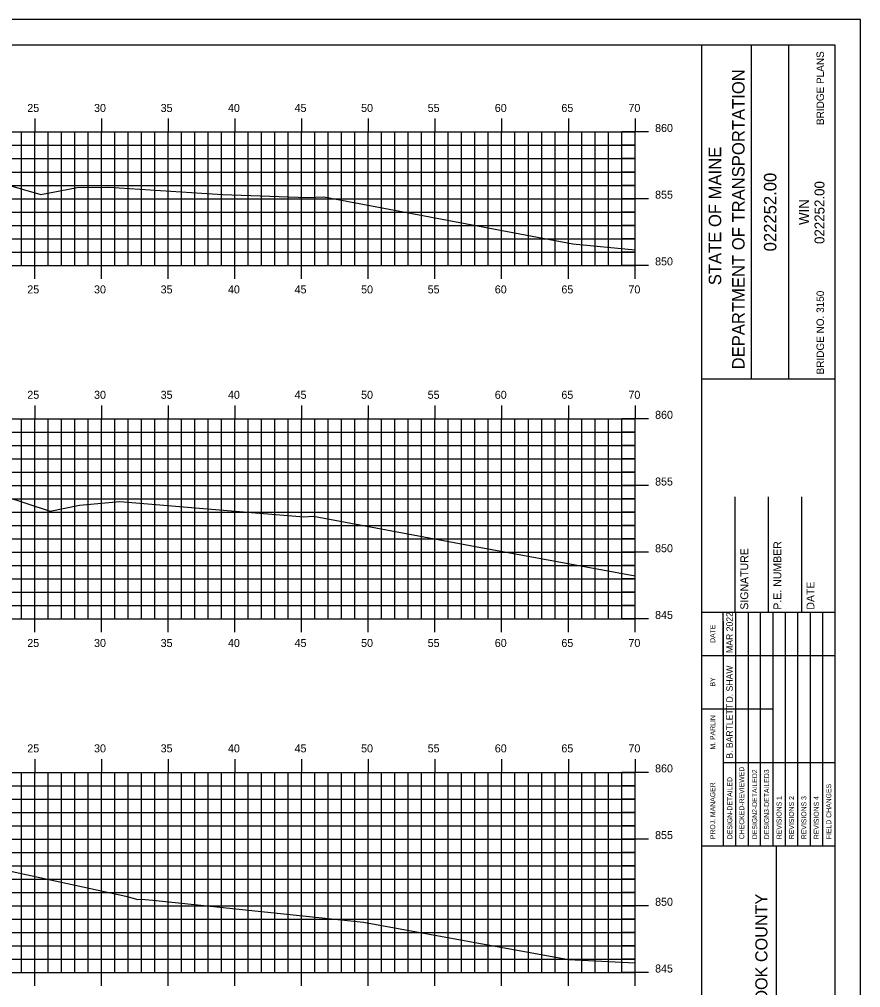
# Model space of a CAD drawing. Extents: x 2194738 to 2195190, y 863888 to 863998.
# Drawn here: x 2194944.1 to 2195007.2, y 863925.8 to 863998.4 of the extents above; entities that cross this region are included whole.
import ezdxf

# ---------------------------------------------------------------- set-up
doc = ezdxf.new("R2010")
doc.units = 0
for name, color, linetype in [('BORDER', 7, 'Continuous'), ('BRIDGE_TITLE', 7, 'Continuous'), ('H_V ANNOTATION', 7, 'Continuous'), ('MAJOR', 7, 'Continuous'), ('MINOR', 7, 'Continuous'), ('PLOT BOUNDARY', 7, 'Continuous'), ('S_Roadway_Centerline', 7, 'Continuous')]:
    doc.layers.add(name, color=color, linetype=linetype)

msp = doc.modelspace()

# ---------------------------------------------------------------- linework, layer by layer
at = {"layer": 'BORDER'}
for p, q in [((2194995.256, 863891.446), (2194995.256, 863996.446)), ((2194998.985, 863971.443), (2194998.985, 863996.443)), ((2195001.78, 863971.443), (2195001.78, 863996.443)), ((2194995.257, 863971.44), (2195005.256, 863971.44)), ((2194997.756, 863953.949), (2194997.756, 863962.596)), ((2195000.256, 863953.949), (2195000.256, 863962.596)), ((2195002.756, 863953.949), (2195002.756, 863962.596)), ((2194995.256, 863953.949), (2195005.256, 863953.949)), ((2194995.256, 863936.449), (2195005.256, 863936.449)), ((2195000.847, 863901.449), (2195000.847, 863936.449))]:
    msp.add_line(p, q, dxfattribs=at)
msp.add_lwpolyline([(2194845.256, 863891.446), (2195005.256, 863891.446), (2195005.256, 863996.446), (2194845.256, 863996.446)], close=True, dxfattribs=at)
for points in [[(2194996.871, 863950.699), (2194996.871, 863953.949)], [(2194997.804, 863936.452), (2194997.804, 863953.949)], [(2194998.735, 863953.949), (2194998.735, 863936.452)], [(2194999.667, 863936.452), (2194999.667, 863953.949)], [(2195000.599, 863936.452), (2195000.599, 863953.949)], [(2195001.53, 863936.452), (2195001.53, 863953.949)], [(2195002.462, 863936.452), (2195002.462, 863953.949)], [(2195003.394, 863936.452), (2195003.394, 863953.949)], [(2195004.325, 863936.452), (2195004.325, 863953.949)], [(2194996.872, 863936.452), (2194996.872, 863953.243)], [(2194995.256, 863950.699), (2195005.256, 863950.699)], [(2194995.256, 863946.699), (2194996.872, 863946.699)], [(2194996.871, 863946.699), (2195000.598, 863946.699)], [(2194996.871, 863942.699), (2195005.256, 863942.699)]]:
    msp.add_lwpolyline(points, dxfattribs=at)
at = {"layer": 'MAJOR'}
for p, q in [((2194945.256, 863990.948), (2194945.256, 863989.946)), ((2194950.256, 863990.948), (2194950.256, 863989.946)), ((2194955.256, 863990.948), (2194955.256, 863989.946)), ((2194960.256, 863990.948), (2194960.256, 863989.946)), ((2194965.256, 863990.948), (2194965.256, 863989.946)), ((2194970.256, 863990.948), (2194970.256, 863989.946)), ((2194975.256, 863990.948), (2194975.256, 863989.946)), ((2194980.256, 863990.948), (2194980.256, 863989.946)), ((2194985.256, 863990.948), (2194985.256, 863989.946)), ((2194990.256, 863990.948), (2194990.256, 863989.946)), ((2194850.256, 863989.946), (2194990.256, 863989.946)), ((2194945.256, 863979.946), (2194945.256, 863989.946)), ((2194950.256, 863979.946), (2194950.256, 863989.946)), ((2194955.256, 863979.946), (2194955.256, 863989.946)), ((2194960.256, 863979.946), (2194960.256, 863989.946)), ((2194965.256, 863979.946), (2194965.256, 863989.946)), ((2194970.256, 863979.946), (2194970.256, 863989.946)), ((2194975.256, 863979.946), (2194975.256, 863989.946)), ((2194980.256, 863979.946), (2194980.256, 863989.946)), ((2194985.256, 863979.946), (2194985.256, 863989.946)), ((2194991.258, 863989.946), (2194989.254, 863989.946)), ((2194990.256, 863979.946), (2194990.256, 863989.946)), ((2194990.256, 863979.946), (2194990.256, 863989.946)), ((2194850.256, 863984.946), (2194990.256, 863984.946)), ((2194991.258, 863984.946), (2194989.254, 863984.946)), ((2194850.256, 863979.946), (2194990.256, 863979.946)), ((2194945.256, 863978.944), (2194945.256, 863979.946)), ((2194950.256, 863978.944), (2194950.256, 863979.946)), ((2194955.256, 863978.944), (2194955.256, 863979.946)), ((2194960.256, 863978.944), (2194960.256, 863979.946)), ((2194965.256, 863978.944), (2194965.256, 863979.946)), ((2194970.256, 863978.944), (2194970.256, 863979.946)), ((2194975.256, 863978.944), (2194975.256, 863979.946)), ((2194980.256, 863978.944), (2194980.256, 863979.946)), ((2194985.256, 863978.944), (2194985.256, 863979.946)), ((2194991.258, 863979.946), (2194989.254, 863979.946)), ((2194990.256, 863978.944), (2194990.256, 863979.946)), ((2194945.256, 863969.448), (2194945.256, 863968.446)), ((2194950.256, 863969.448), (2194950.256, 863968.446)), ((2194955.256, 863969.448), (2194955.256, 863968.446)), ((2194960.256, 863969.448), (2194960.256, 863968.446)), ((2194965.256, 863969.448), (2194965.256, 863968.446)), ((2194970.256, 863969.448), (2194970.256, 863968.446)), ((2194975.256, 863969.448), (2194975.256, 863968.446)), ((2194980.256, 863969.448), (2194980.256, 863968.446)), ((2194985.256, 863969.448), (2194985.256, 863968.446)), ((2194990.256, 863969.448), (2194990.256, 863968.446)), ((2194850.256, 863968.446), (2194990.256, 863968.446)), ((2194945.256, 863953.446), (2194945.256, 863968.446)), ((2194950.256, 863953.446), (2194950.256, 863968.446)), ((2194955.256, 863953.446), (2194955.256, 863968.446)), ((2194960.256, 863953.446), (2194960.256, 863968.446)), ((2194965.256, 863953.446), (2194965.256, 863968.446)), ((2194970.256, 863953.446), (2194970.256, 863968.446)), ((2194975.256, 863953.446), (2194975.256, 863968.446)), ((2194980.256, 863953.446), (2194980.256, 863968.446)), ((2194985.256, 863953.446), (2194985.256, 863968.446)), ((2194991.258, 863968.446), (2194989.254, 863968.446)), ((2194990.256, 863953.446), (2194990.256, 863968.446)), ((2194990.256, 863953.446), (2194990.256, 863968.446)), ((2194850.256, 863963.446), (2194990.256, 863963.446)), ((2194991.258, 863963.446), (2194989.254, 863963.446)), ((2194850.256, 863958.446), (2194990.256, 863958.446)), ((2194991.258, 863958.446), (2194989.254, 863958.446)), ((2194850.256, 863953.446), (2194990.256, 863953.446)), ((2194945.256, 863952.444), (2194945.256, 863953.446)), ((2194950.256, 863952.444), (2194950.256, 863953.446)), ((2194955.256, 863952.444), (2194955.256, 863953.446)), ((2194960.256, 863952.444), (2194960.256, 863953.446)), ((2194965.256, 863952.444), (2194965.256, 863953.446)), ((2194970.256, 863952.444), (2194970.256, 863953.446)), ((2194975.256, 863952.444), (2194975.256, 863953.446)), ((2194980.256, 863952.444), (2194980.256, 863953.446)), ((2194985.256, 863952.444), (2194985.256, 863953.446)), ((2194991.258, 863953.446), (2194989.254, 863953.446)), ((2194990.256, 863952.444), (2194990.256, 863953.446)), ((2194945.256, 863942.948), (2194945.256, 863941.946)), ((2194950.256, 863942.948), (2194950.256, 863941.946)), ((2194955.256, 863942.948), (2194955.256, 863941.946)), ((2194960.256, 863942.948), (2194960.256, 863941.946)), ((2194965.256, 863942.948), (2194965.256, 863941.946)), ((2194970.256, 863942.948), (2194970.256, 863941.946)), ((2194975.256, 863942.948), (2194975.256, 863941.946)), ((2194980.256, 863942.948), (2194980.256, 863941.946)), ((2194985.256, 863942.948), (2194985.256, 863941.946)), ((2194990.256, 863942.948), (2194990.256, 863941.946)), ((2194850.256, 863941.946), (2194990.256, 863941.946)), ((2194945.256, 863926.946), (2194945.256, 863941.946)), ((2194950.256, 863926.946), (2194950.256, 863941.946)), ((2194955.256, 863926.946), (2194955.256, 863941.946)), ((2194960.256, 863926.946), (2194960.256, 863941.946)), ((2194965.256, 863926.946), (2194965.256, 863941.946)), ((2194970.256, 863926.946), (2194970.256, 863941.946)), ((2194975.256, 863926.946), (2194975.256, 863941.946)), ((2194980.256, 863926.946), (2194980.256, 863941.946)), ((2194985.256, 863926.946), (2194985.256, 863941.946)), ((2194991.258, 863941.946), (2194989.254, 863941.946)), ((2194990.256, 863926.946), (2194990.256, 863941.946)), ((2194990.256, 863926.946), (2194990.256, 863941.946)), ((2194850.256, 863936.946), (2194990.256, 863936.946)), ((2194991.258, 863936.946), (2194989.254, 863936.946)), ((2194850.256, 863931.946), (2194990.256, 863931.946)), ((2194991.258, 863931.946), (2194989.254, 863931.946)), ((2194850.256, 863926.946), (2194990.256, 863926.946)), ((2194945.256, 863925.944), (2194945.256, 863926.946)), ((2194950.256, 863925.944), (2194950.256, 863926.946)), ((2194955.256, 863925.944), (2194955.256, 863926.946)), ((2194960.256, 863925.944), (2194960.256, 863926.946)), ((2194965.256, 863925.944), (2194965.256, 863926.946)), ((2194970.256, 863925.944), (2194970.256, 863926.946)), ((2194975.256, 863925.944), (2194975.256, 863926.946)), ((2194980.256, 863925.944), (2194980.256, 863926.946)), ((2194985.256, 863925.944), (2194985.256, 863926.946)), ((2194991.258, 863926.946), (2194989.254, 863926.946)), ((2194990.256, 863925.944), (2194990.256, 863926.946))]:
    msp.add_line(p, q, dxfattribs=at)
at = {"layer": 'MINOR'}
for p, q in [((2194944.256, 863979.946), (2194944.256, 863989.946)), ((2194946.256, 863979.946), (2194946.256, 863989.946)), ((2194947.256, 863979.946), (2194947.256, 863989.946)), ((2194948.256, 863979.946), (2194948.256, 863989.946)), ((2194949.256, 863979.946), (2194949.256, 863989.946)), ((2194951.256, 863979.946), (2194951.256, 863989.946)), ((2194952.256, 863979.946), (2194952.256, 863989.946)), ((2194953.256, 863979.946), (2194953.256, 863989.946)), ((2194954.256, 863979.946), (2194954.256, 863989.946)), ((2194956.256, 863979.946), (2194956.256, 863989.946)), ((2194957.256, 863979.946), (2194957.256, 863989.946)), ((2194958.256, 863979.946), (2194958.256, 863989.946)), ((2194959.256, 863979.946), (2194959.256, 863989.946)), ((2194961.256, 863979.946), (2194961.256, 863989.946)), ((2194962.256, 863979.946), (2194962.256, 863989.946)), ((2194963.256, 863979.946), (2194963.256, 863989.946)), ((2194964.256, 863979.946), (2194964.256, 863989.946)), ((2194966.256, 863979.946), (2194966.256, 863989.946)), ((2194967.256, 863979.946), (2194967.256, 863989.946)), ((2194968.256, 863979.946), (2194968.256, 863989.946)), ((2194969.256, 863979.946), (2194969.256, 863989.946)), ((2194971.256, 863979.946), (2194971.256, 863989.946)), ((2194972.256, 863979.946), (2194972.256, 863989.946)), ((2194973.256, 863979.946), (2194973.256, 863989.946)), ((2194974.256, 863979.946), (2194974.256, 863989.946)), ((2194976.256, 863979.946), (2194976.256, 863989.946)), ((2194977.256, 863979.946), (2194977.256, 863989.946)), ((2194978.256, 863979.946), (2194978.256, 863989.946)), ((2194979.256, 863979.946), (2194979.256, 863989.946)), ((2194981.256, 863979.946), (2194981.256, 863989.946)), ((2194982.256, 863979.946), (2194982.256, 863989.946)), ((2194983.256, 863979.946), (2194983.256, 863989.946)), ((2194984.256, 863979.946), (2194984.256, 863989.946)), ((2194986.256, 863979.946), (2194986.256, 863989.946)), ((2194987.256, 863979.946), (2194987.256, 863989.946)), ((2194988.256, 863979.946), (2194988.256, 863989.946)), ((2194989.256, 863979.946), (2194989.256, 863989.946)), ((2194850.256, 863988.946), (2194990.256, 863988.946)), ((2194990.256, 863988.946), (2194989.254, 863988.946)), ((2194850.256, 863987.946), (2194990.256, 863987.946)), ((2194990.256, 863987.946), (2194989.254, 863987.946)), ((2194850.256, 863986.946), (2194990.256, 863986.946)), ((2194990.256, 863986.946), (2194989.254, 863986.946)), ((2194850.256, 863985.946), (2194990.256, 863985.946)), ((2194990.256, 863985.946), (2194989.254, 863985.946)), ((2194850.256, 863983.946), (2194990.256, 863983.946)), ((2194990.256, 863983.946), (2194989.254, 863983.946)), ((2194850.256, 863982.946), (2194990.256, 863982.946)), ((2194990.256, 863982.946), (2194989.254, 863982.946)), ((2194850.256, 863981.946), (2194990.256, 863981.946)), ((2194990.256, 863981.946), (2194989.254, 863981.946)), ((2194850.256, 863980.946), (2194990.256, 863980.946)), ((2194990.256, 863980.946), (2194989.254, 863980.946)), ((2194944.256, 863953.446), (2194944.256, 863968.446)), ((2194946.256, 863953.446), (2194946.256, 863968.446)), ((2194947.256, 863953.446), (2194947.256, 863968.446)), ((2194948.256, 863953.446), (2194948.256, 863968.446)), ((2194949.256, 863953.446), (2194949.256, 863968.446)), ((2194951.256, 863953.446), (2194951.256, 863968.446)), ((2194952.256, 863953.446), (2194952.256, 863968.446)), ((2194953.256, 863953.446), (2194953.256, 863968.446)), ((2194954.256, 863953.446), (2194954.256, 863968.446)), ((2194956.256, 863953.446), (2194956.256, 863968.446)), ((2194957.256, 863953.446), (2194957.256, 863968.446)), ((2194958.256, 863953.446), (2194958.256, 863968.446)), ((2194959.256, 863953.446), (2194959.256, 863968.446)), ((2194961.256, 863953.446), (2194961.256, 863968.446)), ((2194962.256, 863953.446), (2194962.256, 863968.446)), ((2194963.256, 863953.446), (2194963.256, 863968.446)), ((2194964.256, 863953.446), (2194964.256, 863968.446)), ((2194966.256, 863953.446), (2194966.256, 863968.446)), ((2194967.256, 863953.446), (2194967.256, 863968.446)), ((2194968.256, 863953.446), (2194968.256, 863968.446)), ((2194969.256, 863953.446), (2194969.256, 863968.446)), ((2194971.256, 863953.446), (2194971.256, 863968.446)), ((2194972.256, 863953.446), (2194972.256, 863968.446)), ((2194973.256, 863953.446), (2194973.256, 863968.446)), ((2194974.256, 863953.446), (2194974.256, 863968.446)), ((2194976.256, 863953.446), (2194976.256, 863968.446)), ((2194977.256, 863953.446), (2194977.256, 863968.446)), ((2194978.256, 863953.446), (2194978.256, 863968.446)), ((2194979.256, 863953.446), (2194979.256, 863968.446)), ((2194981.256, 863953.446), (2194981.256, 863968.446)), ((2194982.256, 863953.446), (2194982.256, 863968.446)), ((2194983.256, 863953.446), (2194983.256, 863968.446)), ((2194984.256, 863953.446), (2194984.256, 863968.446)), ((2194986.256, 863953.446), (2194986.256, 863968.446)), ((2194987.256, 863953.446), (2194987.256, 863968.446)), ((2194988.256, 863953.446), (2194988.256, 863968.446)), ((2194989.256, 863953.446), (2194989.256, 863968.446)), ((2194850.256, 863967.446), (2194990.256, 863967.446)), ((2194990.256, 863967.446), (2194989.254, 863967.446)), ((2194850.256, 863966.446), (2194990.256, 863966.446)), ((2194990.256, 863966.446), (2194989.254, 863966.446)), ((2194850.256, 863965.446), (2194990.256, 863965.446)), ((2194990.256, 863965.446), (2194989.254, 863965.446)), ((2194850.256, 863964.446), (2194990.256, 863964.446)), ((2194990.256, 863964.446), (2194989.254, 863964.446)), ((2194850.256, 863962.446), (2194990.256, 863962.446)), ((2194990.256, 863962.446), (2194989.254, 863962.446)), ((2194850.256, 863961.446), (2194990.256, 863961.446)), ((2194990.256, 863961.446), (2194989.254, 863961.446)), ((2194850.256, 863960.446), (2194990.256, 863960.446)), ((2194990.256, 863960.446), (2194989.254, 863960.446)), ((2194850.256, 863959.446), (2194990.256, 863959.446)), ((2194990.256, 863959.446), (2194989.254, 863959.446)), ((2194850.256, 863957.446), (2194990.256, 863957.446)), ((2194990.256, 863957.446), (2194989.254, 863957.446)), ((2194850.256, 863956.446), (2194990.256, 863956.446)), ((2194990.256, 863956.446), (2194989.254, 863956.446)), ((2194850.256, 863955.446), (2194990.256, 863955.446)), ((2194990.256, 863955.446), (2194989.254, 863955.446)), ((2194850.256, 863954.446), (2194990.256, 863954.446)), ((2194990.256, 863954.446), (2194989.254, 863954.446)), ((2194944.256, 863926.946), (2194944.256, 863941.946)), ((2194946.256, 863926.946), (2194946.256, 863941.946)), ((2194947.256, 863926.946), (2194947.256, 863941.946)), ((2194948.256, 863926.946), (2194948.256, 863941.946)), ((2194949.256, 863926.946), (2194949.256, 863941.946)), ((2194951.256, 863926.946), (2194951.256, 863941.946)), ((2194952.256, 863926.946), (2194952.256, 863941.946)), ((2194953.256, 863926.946), (2194953.256, 863941.946)), ((2194954.256, 863926.946), (2194954.256, 863941.946)), ((2194956.256, 863926.946), (2194956.256, 863941.946)), ((2194957.256, 863926.946), (2194957.256, 863941.946)), ((2194958.256, 863926.946), (2194958.256, 863941.946)), ((2194959.256, 863926.946), (2194959.256, 863941.946)), ((2194961.256, 863926.946), (2194961.256, 863941.946)), ((2194962.256, 863926.946), (2194962.256, 863941.946)), ((2194963.256, 863926.946), (2194963.256, 863941.946)), ((2194964.256, 863926.946), (2194964.256, 863941.946)), ((2194966.256, 863926.946), (2194966.256, 863941.946)), ((2194967.256, 863926.946), (2194967.256, 863941.946)), ((2194968.256, 863926.946), (2194968.256, 863941.946)), ((2194969.256, 863926.946), (2194969.256, 863941.946)), ((2194971.256, 863926.946), (2194971.256, 863941.946)), ((2194972.256, 863926.946), (2194972.256, 863941.946)), ((2194973.256, 863926.946), (2194973.256, 863941.946)), ((2194974.256, 863926.946), (2194974.256, 863941.946)), ((2194976.256, 863926.946), (2194976.256, 863941.946)), ((2194977.256, 863926.946), (2194977.256, 863941.946)), ((2194978.256, 863926.946), (2194978.256, 863941.946)), ((2194979.256, 863926.946), (2194979.256, 863941.946)), ((2194981.256, 863926.946), (2194981.256, 863941.946)), ((2194982.256, 863926.946), (2194982.256, 863941.946)), ((2194983.256, 863926.946), (2194983.256, 863941.946)), ((2194984.256, 863926.946), (2194984.256, 863941.946)), ((2194986.256, 863926.946), (2194986.256, 863941.946)), ((2194987.256, 863926.946), (2194987.256, 863941.946)), ((2194988.256, 863926.946), (2194988.256, 863941.946)), ((2194989.256, 863926.946), (2194989.256, 863941.946)), ((2194850.256, 863940.946), (2194990.256, 863940.946)), ((2194990.256, 863940.946), (2194989.254, 863940.946)), ((2194850.256, 863939.946), (2194990.256, 863939.946)), ((2194990.256, 863939.946), (2194989.254, 863939.946)), ((2194850.256, 863938.946), (2194990.256, 863938.946)), ((2194990.256, 863938.946), (2194989.254, 863938.946)), ((2194850.256, 863937.946), (2194990.256, 863937.946)), ((2194990.256, 863937.946), (2194989.254, 863937.946)), ((2194850.256, 863935.946), (2194990.256, 863935.946)), ((2194990.256, 863935.946), (2194989.254, 863935.946)), ((2194850.256, 863934.946), (2194990.256, 863934.946)), ((2194990.256, 863934.946), (2194989.254, 863934.946)), ((2194850.256, 863933.946), (2194990.256, 863933.946)), ((2194990.256, 863933.946), (2194989.254, 863933.946)), ((2194850.256, 863932.946), (2194990.256, 863932.946)), ((2194990.256, 863932.946), (2194989.254, 863932.946)), ((2194850.256, 863930.946), (2194990.256, 863930.946)), ((2194990.256, 863930.946), (2194989.254, 863930.946)), ((2194850.256, 863929.946), (2194990.256, 863929.946)), ((2194990.256, 863929.946), (2194989.254, 863929.946)), ((2194850.256, 863928.946), (2194990.256, 863928.946)), ((2194990.256, 863928.946), (2194989.254, 863928.946)), ((2194850.256, 863927.946), (2194990.256, 863927.946)), ((2194990.256, 863927.946), (2194989.254, 863927.946))]:
    msp.add_line(p, q, dxfattribs=at)
at = {"layer": 'PLOT BOUNDARY'}
msp.add_lwpolyline([(2194837.163, 863888.387), (2195007.163, 863888.387), (2195007.163, 863998.387), (2194837.163, 863998.387)], close=True, dxfattribs=at)
at = {"layer": 'S_Roadway_Centerline'}
for points in [[(2194941.272, 863986.538), (2194945.71, 863985.269), (2194948.444, 863985.778), (2194950.804, 863985.804), (2194959.321, 863985.254), (2194965.713, 863985.028), (2194966.938, 863985.08), (2194985.602, 863981.566), (2194990.256, 863981.1)], [(2194941.149, 863963.242), (2194946.41, 863961.523), (2194948.602, 863961.964), (2194951.629, 863962.255), (2194959.705, 863961.564), (2194965.429, 863961.097), (2194966.146, 863961.14), (2194978.303, 863958.87), (2194990.256, 863956.681)], [(2194940.327, 863935.219), (2194952.094, 863932.661), (2194952.997, 863932.409), (2194953.237, 863932.432), (2194954.116, 863932.357), (2194969.907, 863930.731), (2194985.261, 863927.923), (2194990.256, 863927.664)]]:
    msp.add_lwpolyline(points, dxfattribs=at)

# ---------------------------------------------------------------- texts
at = {"layer": 'BORDER'}
for s, height, p in [('DEPARTMENT OF TRANSPORTATION', 0.93176, (2194998.463, 863972.152)), ('STATE OF MAINE', 0.93176, (2194996.711, 863978.458)), ('022252.00', 0.9318, (2195000.848, 863980.999)), ('022252.00', 0.7453, (2195004.452, 863981.551)), ('WIN', 0.7453, (2195003.293, 863982.976)), ('P.E. NUMBER', 0.59055, (2195001.217, 863954.141)), ('SIGNATURE', 0.5906, (2194998.736, 863954.141)), ('DATE', 0.5906, (2195003.697, 863954.141)), ('MAR 2022', 0.4845, (2194997.579, 863950.897)), ('DATE', 0.3714, (2194996.26, 863951.654)), ('D. SHAW', 0.4845, (2194997.579, 863947.184)), ('BY', 0.3714, (2194996.26, 863948.384)), ('B. BARTLETT', 0.48455, (2194997.579, 863942.972)), ('M. PARLIN', 0.3727, (2194996.26, 863943.656)), ('CHECKED-REVIEWED', 0.37275, (2194998.437, 863936.937)), ('DESIGN2-DETAILED2', 0.37275, (2194999.406, 863936.937)), ('DESIGN3-DETAILED3', 0.37275, (2195000.3, 863936.937)), ('PROJ. MANAGER', 0.37275, (2194996.26, 863936.937)), ('DESIGN-DETAILED', 0.37275, (2194997.543, 863936.937)), ('FIELD CHANGES', 0.37275, (2195004.959, 863936.937)), ('REVISIONS 1', 0.37275, (2195001.232, 863936.937)), ('REVISIONS 2', 0.37275, (2195002.164, 863936.937)), ('REVISIONS 3', 0.37275, (2195003.095, 863936.937)), ('REVISIONS 4', 0.37275, (2195004.027, 863936.937))]:
    msp.add_text(s, height=height, rotation=90, dxfattribs=at).set_placement(p)
at = {"layer": 'BRIDGE_TITLE'}
for s, height, p in [('BRIDGE PLANS', 0.55901, (2195004.414, 863990.47)), ('BRIDGE NO. 3150', 0.55901, (2195004.414, 863971.776)), ('AROOSTOOK COUNTY', 0.90716, (2195000.176, 863919.571))]:
    msp.add_text(s, height=height, rotation=90, dxfattribs=at).set_placement(p)
at = {"layer": 'H_V ANNOTATION'}
for s, p in [('25', (2194944.702, 863991.446)), ('30', (2194949.705, 863991.446)), ('35', (2194954.697, 863991.446)), ('40', (2194959.742, 863991.446)), ('45', (2194964.734, 863991.446)), ('50', (2194969.721, 863991.446)), ('55', (2194974.712, 863991.446)), ('60', (2194979.742, 863991.446)), ('65', (2194984.734, 863991.446)), ('70', (2194989.758, 863991.446)), ('860', (2194991.756, 863989.946)), ('855', (2194991.756, 863984.946)), ('850', (2194991.756, 863979.946)), ('25', (2194944.702, 863977.846)), ('30', (2194949.705, 863977.846)), ('35', (2194954.697, 863977.846)), ('40', (2194959.742, 863977.846)), ('45', (2194964.734, 863977.846)), ('50', (2194969.721, 863977.846)), ('55', (2194974.712, 863977.846)), ('60', (2194979.742, 863977.846)), ('65', (2194984.734, 863977.846)), ('70', (2194989.758, 863977.846)), ('25', (2194944.702, 863969.946)), ('30', (2194949.705, 863969.946)), ('35', (2194954.697, 863969.946)), ('40', (2194959.742, 863969.946)), ('45', (2194964.734, 863969.946)), ('50', (2194969.721, 863969.946)), ('55', (2194974.712, 863969.946)), ('60', (2194979.742, 863969.946)), ('65', (2194984.734, 863969.946)), ('70', (2194989.758, 863969.946)), ('860', (2194991.756, 863968.446)), ('855', (2194991.756, 863963.446)), ('850', (2194991.756, 863958.446)), ('845', (2194991.756, 863953.446)), ('25', (2194944.702, 863951.346)), ('30', (2194949.705, 863951.346)), ('35', (2194954.697, 863951.346)), ('40', (2194959.742, 863951.346)), ('45', (2194964.734, 863951.346)), ('50', (2194969.721, 863951.346)), ('55', (2194974.712, 863951.346)), ('60', (2194979.742, 863951.346)), ('65', (2194984.734, 863951.346)), ('70', (2194989.758, 863951.346)), ('25', (2194944.702, 863943.446)), ('30', (2194949.705, 863943.446)), ('35', (2194954.697, 863943.446)), ('40', (2194959.742, 863943.446)), ('45', (2194964.734, 863943.446)), ('50', (2194969.721, 863943.446)), ('55', (2194974.712, 863943.446)), ('60', (2194979.742, 863943.446)), ('65', (2194984.734, 863943.446)), ('70', (2194989.758, 863943.446)), ('860', (2194991.756, 863941.946)), ('855', (2194991.756, 863936.946)), ('850', (2194991.756, 863931.946)), ('845', (2194991.756, 863926.946))]:
    msp.add_text(s, height=0.6, dxfattribs=at).set_placement(p)

doc.saveas('drawing.dxf')
